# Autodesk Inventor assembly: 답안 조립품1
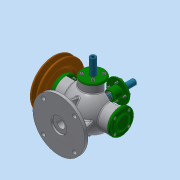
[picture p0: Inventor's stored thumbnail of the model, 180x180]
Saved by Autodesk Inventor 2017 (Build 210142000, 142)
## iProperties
Part Number: 답안 조립품1
Material: 일반
Document SubType Name: Assembly
Designer: MRC
Author: MRC
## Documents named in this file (17)
- C:\Users\MRC\Desktop\600911V1005\답안 조립품1.iam
- C:\Users\MRC\Desktop\600911V1005\본체.ipt
- C:\Users\MRC\Desktop\600911V1005\V-벨트풀리.ipt
- C:\Users\MRC\Desktop\600911V1005\너트 M8x1.ipt
- C:\Users\MRC\Desktop\600911V1005\뒤커버.ipt
- C:\Users\MRC\Desktop\600911V1005\베어링 6202.ipt
- C:\Users\MRC\Desktop\600911V1005\본체커버.ipt
- C:\Users\MRC\Desktop\600911V1005\볼트 M4.ipt
- C:\Users\MRC\Desktop\600911V1005\스프링1.ipt
- C:\Users\MRC\Desktop\600911V1005\스프링2.ipt
- C:\Users\MRC\Desktop\600911V1005\슬라이드 커버.ipt
- C:\Users\MRC\Desktop\600911V1005\슬라이드.ipt
- C:\Users\MRC\Desktop\600911V1005\앞커버.ipt
- C:\Users\MRC\Desktop\600911V1005\오일 실.ipt
- C:\Users\MRC\Desktop\600911V1005\와셔 8x17.ipt
- C:\Users\MRC\Desktop\600911V1005\축.ipt
- C:\Users\MRC\Desktop\600911V1005\키 4x4.ipt
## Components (1 placed, 1 different names)
1. V-벨트풀리:1
